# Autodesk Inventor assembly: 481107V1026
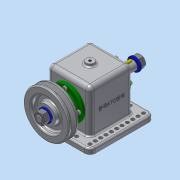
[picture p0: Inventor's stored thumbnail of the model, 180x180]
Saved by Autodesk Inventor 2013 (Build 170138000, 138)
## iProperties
Created: 2018-11
Part Number: 481107V1026
Document SubType Name: Assembly
Designer: Administrator
Author: Administrator
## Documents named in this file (13)
- C:\Users\Administrator\Desktop\481107V1026\481107V1026.iam
- C:\Users\Administrator\Desktop\481107V1026\본체.ipt
- C:\Users\Administrator\Desktop\481107V1026\베어링 6203.ipt
- C:\Users\Administrator\Desktop\481107V1026\볼트 M4.ipt
- C:\Users\Administrator\Desktop\481107V1026\부시.ipt
- C:\Users\Administrator\Desktop\481107V1026\스퍼기어.ipt
- C:\Users\Administrator\Desktop\481107V1026\오일 실 26 38 8.ipt
- C:\Users\Administrator\Desktop\481107V1026\와셔 12x24.ipt
- C:\Users\Administrator\Desktop\481107V1026\축.ipt
- C:\Users\Administrator\Desktop\481107V1026\커버.ipt
- C:\Users\Administrator\Desktop\481107V1026\키 5x5x12.ipt
- C:\Users\Administrator\Desktop\481107V1026\V벨트풀리.ipt
- C:\Users\Administrator\Desktop\481107V1026\너트 M12x1.25.ipt
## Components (1 placed, 1 different names)
1. V벨트풀리:1
